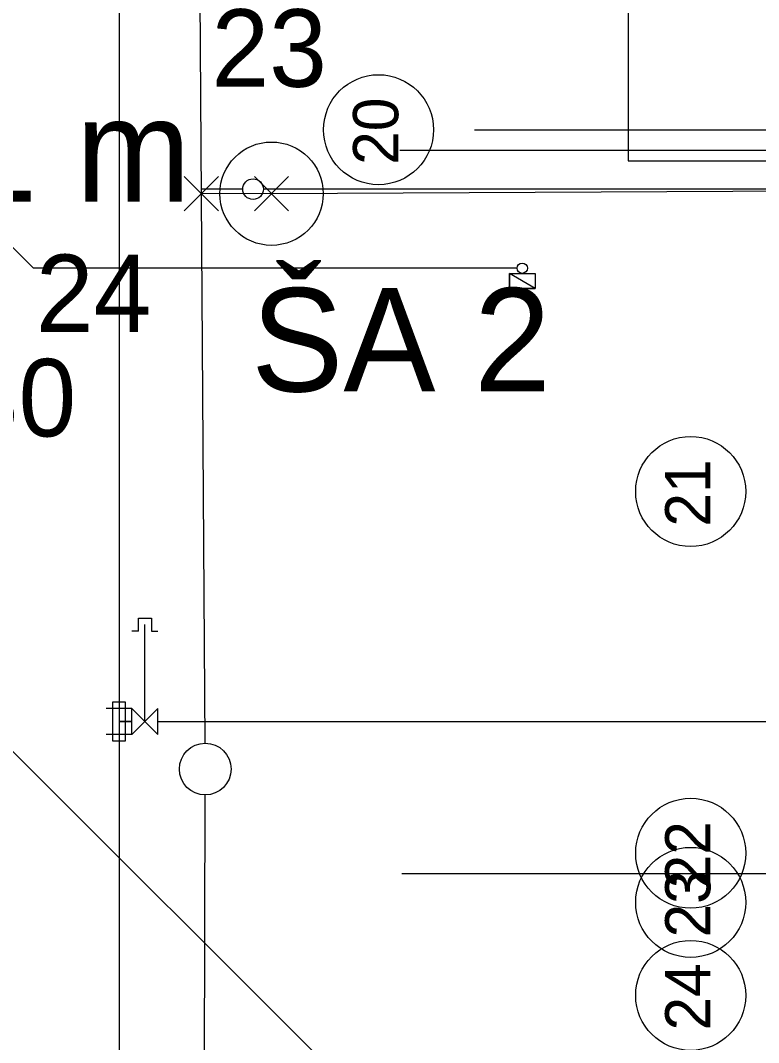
# Model space of a CAD drawing. Extents: x -264031 to -263588, y -1242281 to -1242059.
# Drawn here: x -263926.05 to -263911.77, y -1242227.54 to -1242207.77 of the extents above; entities that cross this region are included whole.
import ezdxf

# ---------------------------------------------------------------- set-up
doc = ezdxf.new("R2010")
doc.units = 0
for name, color, linetype in [('HESCON_OSI_STAVBY_KFA', 7, 'Continuous'), ('KFA_2D_SITUACIA_DSP', 7, 'Continuous'), ('KFA_BODY_CISLO', 7, 'Continuous'), ('KFA_BODY_SYMBOL', 7, 'Continuous'), ('KFA_BODY_VYSKA', 7, 'Continuous'), ('KFA_JESTV_IS_DSP_-_KANAL_SPLASK', 7, 'Continuous'), ('KFA_SO-40-1-II_SK_MER_TRIBUNA_A', 7, 'Continuous'), ('POPIS', 7, 'Continuous')]:
    doc.layers.add(name, color=color, linetype=linetype)

msp = doc.modelspace()

# ---------------------------------------------------------------- linework, layer by layer
at = {"layer": 'HESCON_OSI_STAVBY_KFA'}
msp.add_line((-263917.265, -1242209.882), (-263905.505, -1242209.882), dxfattribs=at)
msp.add_line((-263917.265, -1242209.882), (-263905.505, -1242209.882), dxfattribs=at)
for centre in [(-263919.123, -1242209.882), (-263913.085, -1242216.882), (-263913.085, -1242223.882), (-263913.085, -1242224.832), (-263913.085, -1242226.632)]:
    msp.add_circle(centre, 1.064, dxfattribs=at)
at = {"layer": 'KFA_2D_SITUACIA_DSP'}
for p, q in [((-263924.143, -1242185.14), (-263924.143, -1242250.14)), ((-263908.718, -1242210.282), (-263918.714, -1242210.282)), ((-263921.751, -1242211.032), (-263922.551, -1242211.032)), ((-263903.343, -1242211.032), (-263921.351, -1242211.032)), ((-263925.798, -1242212.562), (-263926.593, -1242211.767)), ((-263916.443, -1242212.562), (-263925.798, -1242212.562)), ((-263916.593, -1242212.952), (-263916.593, -1242212.662)), ((-263916.593, -1242212.662), (-263916.093, -1242212.662)), ((-263916.093, -1242212.952), (-263916.593, -1242212.662)), ((-263916.093, -1242212.952), (-263916.593, -1242212.662)), ((-263916.593, -1242212.662), (-263916.593, -1242212.952)), ((-263916.093, -1242212.662), (-263916.093, -1242212.952)), ((-263916.093, -1242212.952), (-263916.593, -1242212.952)), ((-263916.593, -1242212.952), (-263916.093, -1242212.952)), ((-263923.768, -1242219.582), (-263923.768, -1242219.332)), ((-263923.768, -1242219.332), (-263923.518, -1242219.332)), ((-263923.518, -1242219.332), (-263923.518, -1242219.582)), ((-263923.768, -1242219.582), (-263923.893, -1242219.582)), ((-263923.643, -1242221.332), (-263923.643, -1242219.457)), ((-263923.518, -1242219.582), (-263923.393, -1242219.582)), ((-263924.018, -1242220.957), (-263924.268, -1242220.957)), ((-263924.268, -1242220.957), (-263924.268, -1242221.707)), ((-263924.018, -1242221.707), (-263924.018, -1242220.957)), ((-263923.893, -1242221.082), (-263924.393, -1242221.082)), ((-263923.893, -1242221.582), (-263923.893, -1242221.082)), ((-263923.893, -1242221.082), (-263923.393, -1242221.582)), ((-263923.393, -1242221.082), (-263923.893, -1242221.582)), ((-263923.393, -1242221.582), (-263923.393, -1242221.082)), ((-263924.143, -1242221.332), (-263923.893, -1242221.332)), ((-263923.893, -1242221.332), (-263924.143, -1242221.332)), ((-263923.393, -1242221.332), (-263903.343, -1242221.332)), ((-263923.893, -1242221.582), (-263924.393, -1242221.582)), ((-263924.268, -1242221.707), (-263924.018, -1242221.707)), ((-263916.414, -1242231.691), (-263926.24, -1242221.865)), ((-263908.718, -1242224.282), (-263918.67, -1242224.282))]:
    msp.add_line(p, q, dxfattribs=at)
msp.add_lwpolyline([(-263893.618, -1242118.282), (-263916.093, -1242118.282), (-263916.093, -1242175.482), (-263914.293, -1242175.482), (-263914.293, -1242210.482), (-263893.618, -1242210.482), (-263893.618, -1242166.382), (-263900.043, -1242166.382), (-263900.043, -1242162.382), (-263893.618, -1242162.382)], close=True, dxfattribs=at)
for centre, radius in [((-263921.551, -1242211.032), 0.2), ((-263916.343, -1242212.562), 0.1)]:
    msp.add_circle(centre, radius, dxfattribs=at)
at = {"layer": 'KFA_BODY_SYMBOL'}
for p, q in [((-263922.882, -1242211.451), (-263922.219, -1242210.788)), ((-263922.219, -1242211.451), (-263922.882, -1242210.788)), ((-263921.525, -1242211.451), (-263920.862, -1242210.789)), ((-263920.862, -1242211.451), (-263921.525, -1242210.789))]:
    msp.add_line(p, q, dxfattribs=at)
at = {"layer": 'KFA_JESTV_IS_DSP_-_KANAL_SPLASK'}
for p, q in [((-263922.479, -1242221.753), (-263922.731, -1242184.174)), ((-263922.54, -1242251.195), (-263922.477, -1242222.753))]:
    msp.add_line(p, q, dxfattribs=at)
msp.add_circle((-263922.476, -1242222.253), 0.5, dxfattribs=at)
at = {"layer": 'KFA_SO-40-1-II_SK_MER_TRIBUNA_A'}
msp.add_lwpolyline([(-263903.343, -1242211.032), (-263921.193, -1242211.12), (-263922.55, -1242211.119)], dxfattribs=at)
msp.add_circle((-263921.193, -1242211.12), 1, dxfattribs=at)

# ---------------------------------------------------------------- texts
at = {"layer": 'HESCON_OSI_STAVBY_KFA'}
for s, p in [('20', (-263918.742, -1242210.562)), ('21', (-263912.704, -1242217.562)), ('22', (-263912.704, -1242224.562)), ('23', (-263912.704, -1242225.512)), ('24', (-263912.704, -1242227.312))]:
    msp.add_text(s, height=0.875, rotation=90, dxfattribs=at).set_placement(p)
at = {"layer": 'KFA_BODY_CISLO'}
for s, p in [('23', (-263922.354, -1242209.052)), ('24', (-263925.752, -1242213.799))]:
    msp.add_text(s, height=1.5, dxfattribs=at).set_placement(p)
at = {"layer": 'KFA_BODY_VYSKA'}
msp.add_text('233.30', height=1.5, dxfattribs=at).set_placement((-263931.107, -1242215.817))
at = {"layer": 'POPIS'}
for s, p in [('KA2, DN150 - 19,21 m', (-263949.659, -1242211.276)), ('ŠA 2', (-263921.588, -1242214.947))]:
    msp.add_text(s, height=2, dxfattribs=at).set_placement(p)

doc.saveas('drawing.dxf')
